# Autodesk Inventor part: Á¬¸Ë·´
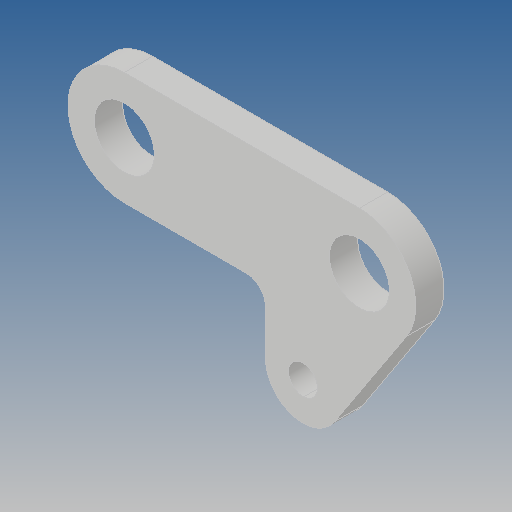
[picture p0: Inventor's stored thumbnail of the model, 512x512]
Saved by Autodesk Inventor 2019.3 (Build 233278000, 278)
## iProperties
Created: 2017-12
Part Number: Á¬¸Ë·´
Material: Ogólny
Document SubType Name: Modeling
Designer: Admin
Density: 1 g/cm^3
Appearance: Domyślna
Author: Admin
Revision Number: ÈÎºÎ
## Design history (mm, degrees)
feature "ÇÐ³ý-À­Éì2"
node "Bryła1"
